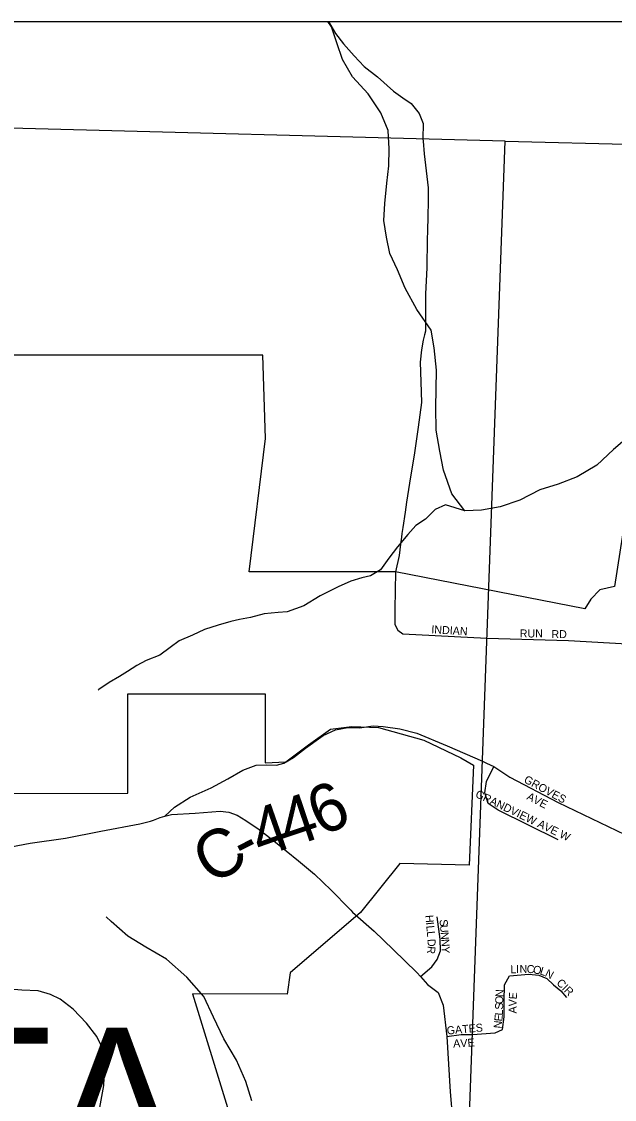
# Model space of a CAD drawing. Extents: x -84548 to 2262448, y -162180 to 525962.
# Drawn here: x 59468 to 63175, y 164137 to 170872 of the extents above; entities that cross this region are included whole.
import ezdxf

# ---------------------------------------------------------------- set-up
doc = ezdxf.new("R2010")
doc.units = 0
for name, color, linetype in [('GM_P_US_Location', 7, 'Continuous'), ('GM_X_County', 7, 'Continuous'), ('GM_X_County_Road', 7, 'Continuous'), ('GM_X_Hydro', 7, 'Continuous'), ('GM_X_Major_Lake_Text', 7, 'Continuous'), ('GM_X_Minor_Lake', 7, 'Continuous'), ('GM_X_Minor_River_Text', 7, 'Continuous'), ('GM_X_State_Route', 7, 'Continuous'), ('GM_X_Township_Subdivision_Text', 7, 'Continuous'), ('GM_X_US_Location', 7, 'Continuous'), ('GM_X_US_Route', 7, 'Continuous')]:
    doc.layers.add(name, color=color, linetype=linetype)

msp = doc.modelspace()

# ---------------------------------------------------------------- linework, layer by layer
at = {"layer": 'GM_X_County'}
msp.add_line((31945.4, 170872.5), (67849.4, 170872.5), dxfattribs=at)
at = {"layer": 'GM_X_Hydro'}
for p, q in [((62491.5, 170125.7), (56872.3, 170273.8)), ((62063.9, 158472), (62491.5, 170125.7)), ((62491.5, 170125.7), (67849.4, 169984.2))]:
    msp.add_line(p, q, dxfattribs=at)
at = {"layer": 'GM_X_Major_Lake_Text'}
for points in [[(59158.4, 166124.1), (59151.3, 166085), (59140, 165982.8), (59142.8, 165884.7), (59163.8, 165760.7), (59234.1, 165733.2), (59326.3, 165717.8), (59400.3, 165716.4), (59522.2, 165739.4), (59742.2, 165769.1), (59964, 165812.8), (60207.8, 165858.8), (60266.7, 165873.5)], [(60266.7, 165873.5), (60273.8, 165875.3), (60292.2, 165882.8), (60333.6, 165899.8), (60362.9, 165907.4), (60405.5, 165918.4), (60553.6, 165925.5), (60709.6, 165938.7), (60763.7, 165933.1), (60815.9, 165913.5), (60870.2, 165879.9), (60952.7, 165824.4), (61045.3, 165753), (61200.4, 165628), (61299.1, 165544.7), (61404, 165445.3), (61517.6, 165328.3)], [(61517.6, 165328.3), (61526.4, 165319.2), (61537.2, 165308.1), (61672.2, 165189), (61791.2, 165073.7), (61940.4, 164930.6), (61962.3, 164905.9), (62007.1, 164855), (62073, 164806.4), (62104, 164726.7), (62126.2, 164530.4), (62148.5, 164185.1), (62161.8, 164013)]]:
    msp.add_lwpolyline(points, dxfattribs=at)
at = {"layer": 'GM_X_Minor_Lake'}
for points in [[(61387.4, 170872.5), (61430.7, 170797.5), (61480.1, 170732.4), (61547.7, 170657.7), (61611.2, 170590.9), (61694.6, 170526.6), (61794.6, 170436.6), (61851.8, 170396.2), (61904.3, 170360.4), (61954.4, 170298.3), (61978.3, 170236.2), (61978, 170139.3), (61979.2, 170124.5)], [(61979.2, 170124.5), (61985.5, 170045.3), (62009.6, 169834.1), (62011.5, 169748), (62007.4, 169655.8), (62005.5, 169562.4), (62004.5, 169513.5), (62002.3, 169333.1), (61993.8, 169170.7), (61994.1, 169066.5), (61993.6, 168992.4), (61992.8, 168938.3), (61987.3, 168914)], [(61987.3, 168914), (61980, 168881.9), (61969.3, 168821.6), (61961, 168743.3), (61963.6, 168621.1), (61968.3, 168493), (61947.7, 168338.3), (61925.1, 168177.6), (61893.1, 167988.6), (61875.8, 167868.4)], [(61875.8, 167868.4), (61867, 167807.7), (61852, 167711.9)], [(61852, 167711.9), (61845.9, 167673.1), (61843.1, 167651.1), (61837.7, 167607.4)]]:
    msp.add_lwpolyline(points, dxfattribs=at)
at = {"layer": 'GM_X_Minor_River_Text'}
for points in [[(60362.9, 165907.4), (60424, 165964.1), (60522.7, 166026.3), (60653.5, 166085.2), (60758.3, 166141.5), (60851.2, 166195.6), (60934.6, 166225.4), (60996.6, 166228.7), (61062.6, 166226.1), (61108.4, 166239.1), (61167.7, 166274.4), (61242.5, 166332.1), (61352.8, 166410.6), (61430.1, 166446.3), (61507.8, 166461.9), (61581.9, 166459.5), (61667.3, 166472.7), (61728.6, 166467.7), (61834.1, 166453), (61939.6, 166426.1), (62128.4, 166347.6), (62349.3, 166250.3), (62375.6, 166238.2)], [(59952.8, 164063.1), (59981.4, 164223.9), (59988.3, 164364.3), (59976.4, 164454.2), (59938.7, 164529.5), (59872.9, 164614.3), (59791, 164700.7), (59709.6, 164763), (59648.9, 164793.8), (59572.3, 164816.2), (59470.2, 164820.1), (59339.9, 164831.3)]]:
    msp.add_lwpolyline(points, dxfattribs=at)
at = {"layer": 'GM_X_State_Route'}
for points in [[(63285, 168295.4), (63169, 168199.1), (63065, 168100.8), (62943, 168028.6), (62823, 167982.4), (62709, 167946.3), (62583, 167882.1), (62461, 167840), (62345, 167819.9), (62239.1, 167815.9), (62159.1, 167922.2), (62107.1, 168068.7), (62083.1, 168189), (62061.2, 168319.4), (62059.2, 168459.9), (62061.2, 168576.2), (62063.2, 168694.6), (62047.3, 168833), (62029.3, 168943.3), (61939.3, 169073.7), (61867.3, 169206.1), (61819.4, 169320.4), (61771.4, 169422.8), (61749.4, 169525.1), (61733.5, 169629.4), (61739.5, 169735.7), (61751.5, 169862.1), (61765.5, 169970.4), (61767.5, 170076.7), (61759.6, 170191.1), (61713.6, 170301.4), (61635.6, 170421.8), (61537.7, 170528.1), (61475.7, 170636.4), (61439.7, 170738.7), (61405.7, 170839), (61383.9, 170872.5)], [(62239.1, 167815.9), (62118.6, 167852.4), (62053.9, 167823.8), (61994.6, 167762.9), (61933.7, 167724.1), (61882.4, 167667.1), (61818.7, 167590.3), (61765.2, 167519.3), (61711.5, 167446.2), (61650.7, 167409.5), (61596.4, 167396.6), (61525.9, 167376.1), (61447, 167339.8), (61335.7, 167284.1), (61232.3, 167222.2), (61129.4, 167184.3), (61073.3, 167179.6), (60985, 167171.5), (60898.4, 167149.3), (60830.1, 167136.8), (60775.8, 167124), (60697.2, 167101.6), (60612.6, 167073.4), (60535.7, 167039), (60452.9, 167002.7), (60398, 166961.8), (60332.9, 166913.1), (60246.1, 166879), (60189.3, 166848.1), (60130.5, 166811.3), (60079.8, 166780.3), (60014.9, 166741.7), (59951.9, 166698.9), (59946, 166695.4)], [(60906.9, 164128.8), (60870.9, 164249.1), (60810.9, 164383.5), (60732.9, 164515.9), (60668.9, 164650.3), (60606.9, 164780.7), (60500.9, 164901.1), (60375, 165013.4), (60245, 165089.6), (60133, 165157.8), (60029, 165250.1), (59997, 165278.2)]]:
    msp.add_lwpolyline(points, dxfattribs=at)
at = {"layer": 'GM_X_Township_Subdivision_Text'}
for points in [[(67849.4, 159186.1), (67849.4, 170872.5), (66665.9, 170872.5), (66530.9, 170764.5), (66064.8, 170139.6), (66143.6, 169918.7), (66422.6, 170057.4), (66043.7, 169387.3), (65881.1, 169424.9), (65568, 169772.7), (65404.7, 169609.4), (64960, 169148.9), (64695, 168844), (64595.1, 168695.9), (63390, 168723.1), (63175.6, 167343.1), (63083.4, 167321.6), (63027, 167263.7), (62990.6, 167201.8), (61806.2, 167434.3), (60891.2, 167434.3), (60993.6, 168267), (60975.5, 168788.1), (57658.2, 168787.9)], [(57433.2, 166049.8), (60133.2, 166050), (60133.2, 166670.9), (60991.2, 166670.9), (60991.2, 166240.6), (61121.3, 166245.9), (61262.1, 166353.4), (61398.8, 166450.8), (61533, 166468.1), (61699.1, 166461.2), (61982.9, 166381.5), (62214.5, 166271.9), (62294.3, 166225.4), (62266.6, 165600.1), (61834.2, 165610.5), (61588.2, 165305.2), (61147.6, 164928.7), (61128.9, 164794.5), (60536.3, 164797.8), (60966.7, 163404.3)]]:
    msp.add_lwpolyline(points, dxfattribs=at)
at = {"layer": 'GM_X_US_Location'}
for points in [[(61837.7, 167607.4), (61828.8, 167536.5), (61806.2, 167434.3), (61802.5, 167201.4), (61801.5, 167105.2), (61819.9, 167069.3), (61852.1, 167045.6), (62377.6, 167019.6), (62888.7, 167004.9), (63585.3, 166965.6)], [(62375.6, 166238.2), (62420.3, 166217.6), (62520.8, 166151.4), (62822.5, 165991.9), (63396.4, 165717.2), (63506.8, 165668.2), (63602.5, 165641.2), (63708.6, 165547.1)], [(62447.3, 165945.3), (62385.9, 165987), (62363.9, 166053.2), (62376.1, 166124.4), (62420.3, 166217.6)], [(62822.5, 165758.9), (62447.3, 165945.3)], [(61962.3, 164905.9), (62033.5, 164965.1), (62067.1, 165011.5), (62088.5, 165065.8), (62085.8, 165137.9), (62066.3, 165278)], [(62474.5, 164573.2), (62486.3, 164654.4), (62484.8, 164751.8), (62488.1, 164852.9), (62518.7, 164909.7)], [(62518.7, 164909.7), (62639.8, 164920), (62703.2, 164912.7), (62753.4, 164893.5), (62794.7, 164853.6), (62840.5, 164816.7), (62875.9, 164773.9)], [(62126.2, 164530.4), (62216.2, 164543.7), (62286.7, 164543.8), (62428.7, 164552.5), (62474.5, 164573.2)]]:
    msp.add_lwpolyline(points, dxfattribs=at)

# ---------------------------------------------------------------- texts
at = {"layer": 'GM_P_US_Location'}
msp.add_text('MARIETTA', height=900, rotation=0.00001, dxfattribs=at).set_placement((54377.7, 163685.6))
at = {"layer": 'GM_X_County_Road'}
for s, rotation, p in [('6', 24.41862, (61341.6, 165777.4)), ('4', 18.62254, (61135.6, 165706.2)), ('4', 19.30061, (60962.1, 165645.5)), ('C', 30.34156, (60653.5, 165471.5)), ('-', 27.00489, (60862.1, 165593.7))]:
    msp.add_text(s, height=300, rotation=rotation, dxfattribs=at).set_placement(p)
at = {"layer": 'GM_X_US_Route'}
for s, rotation, p in [('INDIAN', 356.49615, (62029.2, 167050.4)), ('RUN', 0.00001, (62583, 167024)), ('RD', 0.00001, (62781, 167019.6)), ('GROVES', 331.63204, (62604.8, 166121)), ('GRANDVIEW AVE W', 334.38928, (62300.9, 166028.8)), ('AVE', 332.52612, (62622.5, 166014.5)), ('H', 275.49422, (61992.1, 165287.5)), ('I', 275.51418, (61996.3, 165243.7)), ('L', 275.49992, (61998.4, 165221.8)), ('S', 274.84193, (62081.4, 165260.5)), ('U', 274.83626, (62084.3, 165225.5)), ('L', 275.36263, (62001.8, 165186.8)), ('N', 274.85386, (62088.1, 165181.6)), ('R', 263.37954, (62007.8, 165097.4)), ('D', 272.20807, (62006, 165139.3)), ('N', 274.83626, (62091.8, 165137.8)), ('Y', 269.6503, (62095.4, 165095.1)), ('L', 1.70798, (62525.4, 164925.2)), ('I', 1.73882, (62560.6, 164926.3)), ('N', 1.70525, (62582.6, 164926.9)), ('C', 356.61001, (62625.4, 164928.3)), ('O', 350.53768, (62663.5, 164926.1)), ('L', 342.2777, (62705.1, 164919.3)), ('N', 332.95603, (62736.6, 164909.4)), ('CIR', 315, (62809.3, 164861.1)), ('N', 88.53466, (62480.6, 164776.4)), ('O', 88.53466, (62479.5, 164732.4)), ('V', 88.29507, (62563, 164718.1)), ('E', 85.98055, (62564.2, 164761.5)), ('L', 87.78114, (62477.2, 164661.3)), ('S', 88.49989, (62478.6, 164697.2)), ('A', 89.86885, (62562.9, 164674.4)), ('GATES', 5.07993, (62128.8, 164542.4)), ('N', 83.80222, (62468.7, 164578.8)), ('E', 84.36447, (62473.5, 164623.1)), ('A', 2.06569, (62167.8, 164461.5)), ('V', 2.54096, (62212.2, 164463.1)), ('E', 5.40755, (62258.9, 164465.2))]:
    msp.add_text(s, height=50, rotation=rotation, dxfattribs=at).set_placement(p)

doc.saveas('drawing.dxf')
